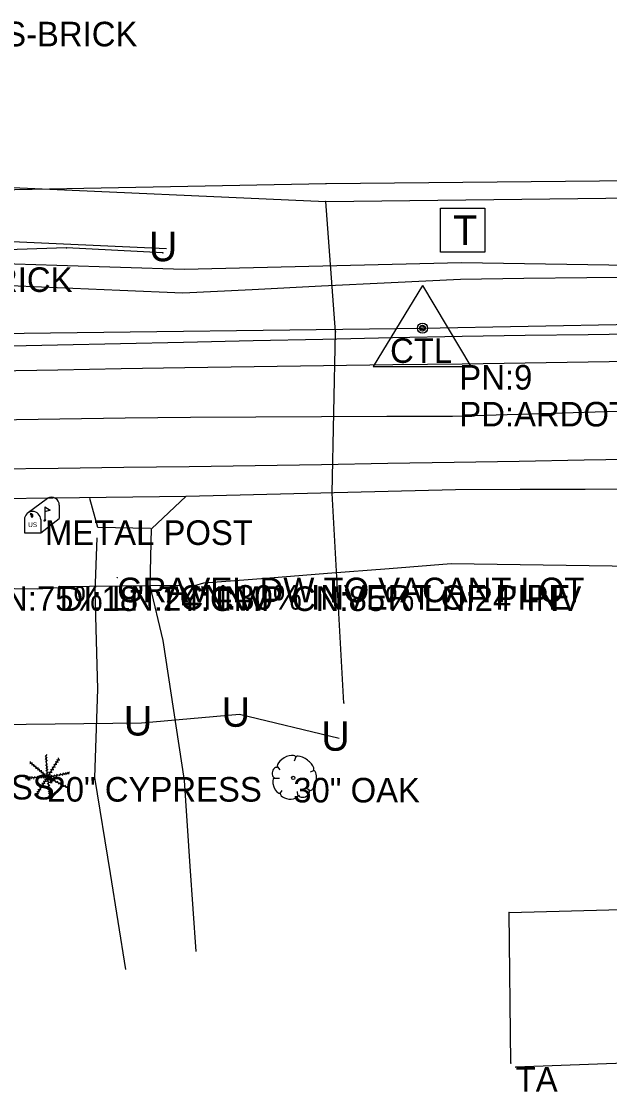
# Model space of a CAD drawing. Extents: x 1800653 to 1804042, y 522635 to 523313.
# Drawn here: x 1803016.3 to 1803136, y 522858.3 to 523076 of the extents above; entities that cross this region are included whole.
import ezdxf

# ---------------------------------------------------------------- set-up
doc = ezdxf.new("R2010")
doc.units = 0
for name, color, linetype in [('Default', 7, 'Continuous'), ('S_BASELINE', 7, 'Continuous'), ('S_BUILDING', 7, 'Continuous'), ('S_BUILDING_ANNOT', 7, 'Continuous'), ('S_DITCHLINE', 7, 'Continuous'), ('S_DRG_PT_SYM', 7, 'Continuous'), ('S_DRIVEWAY', 7, 'Continuous'), ('S_EDGE_PAVEMENT', 7, 'Continuous'), ('S_FIBER_OPTIC_CABLE', 7, 'Continuous'), ('S_GAS_UTILITIES', 7, 'Continuous'), ('S_MAILBOX', 7, 'Continuous'), ('S_MAILBOX_ANNOT', 7, 'Continuous'), ('S_MSC_PT_SYM', 7, 'Continuous'), ('S_PAVEMENT_CROWN', 7, 'Continuous'), ('S_PRIMARY_CTL', 7, 'Continuous'), ('S_PRIMARY_CTL_ANNOT', 7, 'Continuous'), ('S_SHOULDER', 7, 'Continuous'), ('S_SIDE_DRAIN', 7, 'Continuous'), ('S_SIDE_DRAIN_ANNOT', 7, 'Continuous'), ('S_STR_PT_SYM', 7, 'Continuous'), ('S_SURVEY_TEXT_ANNOT', 7, 'Continuous'), ('S_TELEPHONE_UTILITIES', 7, 'Continuous'), ('S_TREE', 7, 'Continuous'), ('S_TREE_ANNOT', 7, 'Continuous'), ('S_UNDERGROUND_CABLE', 7, 'Continuous'), ('S_UTL_PT_SYM', 7, 'Continuous'), ('S_WATER_UTILITIES', 7, 'Continuous')]:
    doc.layers.add(name, color=color, linetype=linetype)

msp = doc.modelspace()

# ---------------------------------------------------------------- linework, layer by layer
at = {"layer": 'S_BASELINE'}
for p, q in [((1803097.96, 523013.6), (1803914.71, 523028.84)), ((1802220.63, 523002.66), (1803097.96, 523013.6))]:
    msp.add_line(p, q, dxfattribs=at)
at = {"layer": 'S_BUILDING'}
for p, q in [((1803115.61, 522894.68), (1803141.73, 522895.4)), ((1803115.93, 522864.06), (1803115.61, 522894.68)), ((1803174.89, 522865.35), (1803116.93, 522863.25))]:
    msp.add_line(p, q, dxfattribs=at)
at = {"layer": 'S_DITCHLINE'}
for points in [[(1802954.76, 523027.19), (1802965.25, 523026.85), (1802981.47, 523027.06), (1802997.7, 523027.27), (1803010.63, 523026.85), (1803023.56, 523026.42), (1803036.49, 523025.99), (1803049.42, 523025.57), (1803063.54, 523025.91), (1803077.66, 523026.26), (1803091.77, 523026.61), (1803105.89, 523026.96), (1803118.74, 523026.75), (1803131.59, 523026.53), (1803144.45, 523026.32), (1803157.3, 523026.11), (1803171.75, 523026.51), (1803186.19, 523026.9), (1803200.64, 523027.3), (1803215.09, 523027.7), (1803229.41, 523027.72), (1803243.73, 523027.74), (1803258.05, 523027.76), (1803272.38, 523027.78)], [(1802954.86, 523026.08), (1802964.7, 523024.61), (1802981.39, 523023.77), (1802998.08, 523022.92), (1803010.85, 523022.39), (1803023.62, 523021.85), (1803036.38, 523021.31), (1803049.15, 523020.77), (1803063.29, 523021.48), (1803077.43, 523022.18), (1803091.58, 523022.88), (1803105.72, 523023.58), (1803118.57, 523023.74), (1803131.43, 523023.9), (1803144.29, 523024.05), (1803157.14, 523024.21), (1803171.66, 523024.43), (1803186.19, 523024.65), (1803200.71, 523024.88), (1803215.23, 523025.1), (1803229.37, 523025.17), (1803243.51, 523025.24), (1803257.65, 523025.32), (1803271.78, 523025.39)], [(1803049.77, 522960.68), (1803053.46, 522961.77), (1803066.04, 522962.75), (1803078.62, 522963.73), (1803091.2, 522964.71), (1803103.78, 522965.69), (1803117.85, 522965.49), (1803131.92, 522965.3), (1803146, 522965.1), (1803160.07, 522964.91), (1803174.22, 522961.96)], [(1802962.08, 522882.48), (1802961.64, 522899.88), (1802961.2, 522917.27), (1802961.74, 522932.63), (1802962.27, 522947.99), (1802966.05, 522961.46), (1802981.02, 522961.17), (1802996, 522960.89), (1803019.65, 522960.53), (1803023.7, 522960.83)]]:
    msp.add_lwpolyline(points, dxfattribs=at)
at = {"layer": 'S_DRG_PT_SYM'}
for points in [[(1803048.53, 522961.31), (1803048.53, 522961.36), (1803048.53, 522961.31), (1803048.48, 522961.31), (1803048.53, 522961.31), (1803048.53, 522961.26), (1803048.53, 522961.31), (1803048.58, 522961.31)], [(1803024.08, 522961.05), (1803024.08, 522961.1), (1803024.08, 522961.05), (1803024.03, 522961.05), (1803024.08, 522961.05), (1803024.08, 522961), (1803024.08, 522961.05), (1803024.13, 522961.05)]]:
    msp.add_lwpolyline(points, dxfattribs=at)
at = {"layer": 'S_DRIVEWAY'}
for points in [[(1803042.57, 522972.81), (1803031.87, 522973.02), (1803030.22, 522978.97)], [(1803042.77, 522972.79), (1803049.84, 522979.41)], [(1803051.89, 522886.77), (1803050.7, 522904.15), (1803049.52, 522921.53), (1803047.34, 522935.77), (1803045.16, 522950.01), (1803042.51, 522961.15), (1803042.81, 522972.85)], [(1803037.6, 522883.12), (1803034.45, 522902.66), (1803031.29, 522922.19), (1803031.9, 522940.15), (1803031.35, 522959.89), (1803031.72, 522970.95)]]:
    msp.add_lwpolyline(points, dxfattribs=at)
at = {"layer": 'S_EDGE_PAVEMENT'}
for points in [[(1803010.82, 523004.9), (1803023.74, 523005.13), (1803036.65, 523005.36), (1803049.57, 523005.6), (1803063.69, 523005.79), (1803077.82, 523005.98), (1803091.94, 523006.17), (1803106.07, 523006.37), (1803118.88, 523006.55), (1803131.69, 523006.74), (1803144.5, 523006.93)], [(1802793.98, 522981.33), (1802808.56, 522981.56), (1802832.98, 522981.95), (1802857.39, 522982.34), (1802874.9, 522982.71), (1802892.4, 522983.08), (1802910.08, 522983.28), (1802927.76, 522983.47), (1802945.52, 522983.73), (1802963.29, 522983.99), (1802980.26, 522984.41), (1802997.22, 522984.84), (1803010.53, 522984.99), (1803023.83, 522985.13), (1803037.14, 522985.28), (1803050.45, 522985.42), (1803063.93, 522985.65), (1803077.42, 522985.88), (1803090.9, 522986.1), (1803104.39, 522986.33), (1803117.62, 522986.56), (1803130.85, 522986.79), (1803144.08, 522987.01)]]:
    msp.add_lwpolyline(points, dxfattribs=at)
at = {"layer": 'S_FIBER_OPTIC_CABLE'}
for p, q in [((1803025.5, 523029.94), (1802984.52, 523028.61)), ((1803045.14, 523028.93), (1803025.5, 523029.94))]:
    msp.add_line(p, q, dxfattribs=at)
at = {"layer": 'S_GAS_UTILITIES'}
for p, q in [((1802933.65, 523045.78), (1803078.29, 523039.38)), ((1803078.29, 523039.38), (1803309.15, 523042.1)), ((1803080.27, 523012.85), (1803078.29, 523039.38)), ((1803079.56, 522980.04), (1803080.27, 523012.85)), ((1803081.98, 522937.31), (1803079.56, 522980.04))]:
    msp.add_line(p, q, dxfattribs=at)
at = {"layer": 'S_MAILBOX'}
for p, q in [((1803017.48, 522975.92), (1803021.61, 522979.03)), ((1803021.09, 522977.21), (1803021.09, 522974.49)), ((1803024.04, 522977.55), (1803024.04, 522974.84)), ((1803016.92, 522974.64), (1803016.92, 522971.93)), ((1803020.25, 522971.93), (1803024.04, 522974.84)), ((1803020.25, 522974.64), (1803020.25, 522971.93)), ((1803016.92, 522971.93), (1803020.25, 522971.93))]:
    msp.add_line(p, q, dxfattribs=at)
for points in [[(1803021.09, 522977.21), (1803022.2, 522976.54), (1803021.09, 522976.19)], [(1803018.11, 522975.76), (1803018.33, 522975.62), (1803018.33, 522975.23), (1803018.63, 522975.23), (1803018.63, 522975.59), (1803018.44, 522975.84), (1803018.11, 522975.79)]]:
    msp.add_lwpolyline(points, dxfattribs=at)
for centre, end in [((1803022.38, 522977.55), 117.5718), ((1803018.59, 522974.64), 180)]:
    msp.add_arc(centre, 1.66, 0, end, dxfattribs=at)
msp.add_ellipse((1803021.09, 522974.49), major_axis=(0.145, 0.132), ratio=0.564646, dxfattribs=at)
at = {"layer": 'S_MSC_PT_SYM'}
msp.add_lwpolyline([(1803035.83, 522962.83), (1803035.83, 522962.88), (1803035.83, 522962.83), (1803035.78, 522962.83), (1803035.83, 522962.83), (1803035.83, 522962.78), (1803035.83, 522962.83), (1803035.88, 522962.83)], dxfattribs=at)
at = {"layer": 'S_PAVEMENT_CROWN'}
msp.add_lwpolyline([(1802794.02, 522991.35), (1802808.65, 522991.45), (1802833.37, 522992.27), (1802858.09, 522993.08), (1802875.18, 522993.01), (1802892.27, 522992.94), (1802910.76, 522993.2), (1802929.25, 522993.47), (1802946.96, 522993.71), (1802964.67, 522993.95), (1802981.09, 522994.36), (1802997.51, 522994.76), (1803010.81, 522994.95), (1803024.11, 522995.13), (1803037.42, 522995.32), (1803050.72, 522995.5), (1803064.06, 522995.56), (1803077.39, 522995.61), (1803090.73, 522995.66), (1803104.06, 522995.72), (1803117.45, 522996.1), (1803130.84, 522996.49), (1803144.23, 522996.88)], dxfattribs=at)
at = {"layer": 'S_PRIMARY_CTL'}
for p, q in [((1803097.96, 523022.3), (1803087.93, 523005.79)), ((1803097.96, 523022.3), (1803107.78, 523005.79)), ((1803087.93, 523005.79), (1803107.78, 523005.79))]:
    msp.add_line(p, q, dxfattribs=at)
for radius in [1.04, 0.609, 0.344]:
    msp.add_circle((1803097.96, 523013.6), radius, dxfattribs=at)
at = {"layer": 'S_SHOULDER'}
for points in [[(1803010.87, 523009.91), (1803023.68, 523010.2), (1803036.48, 523010.48), (1803049.29, 523010.77), (1803063.49, 523011.08), (1803077.68, 523011.38), (1803091.88, 523011.69), (1803106.07, 523012), (1803118.87, 523012.17), (1803131.66, 523012.34), (1803144.46, 523012.52)], [(1802793.86, 522975.94), (1802808.36, 522976.14), (1802832.74, 522976.63), (1802857.12, 522977.13), (1802874.52, 522977.23), (1802891.91, 522977.33), (1802909.78, 522977.47), (1802927.64, 522977.61), (1802945.31, 522977.97), (1802962.99, 522978.33), (1802984.7, 522978.6), (1803006.42, 522978.88), (1803028.14, 522979.15), (1803049.85, 522979.42), (1803063.55, 522979.76), (1803077.25, 522980.09), (1803090.95, 522980.43), (1803104.65, 522980.76), (1803117.85, 522980.81), (1803131.05, 522980.86), (1803144.24, 522980.9)]]:
    msp.add_lwpolyline(points, dxfattribs=at)
at = {"layer": 'S_SIDE_DRAIN'}
msp.add_line((1803024.08, 522961.05), (1803048.53, 522961.31), dxfattribs=at)
at = {"layer": 'S_STR_PT_SYM'}
for points in [[(1803115.61, 522894.68), (1803115.61, 522894.73), (1803115.61, 522894.68), (1803115.56, 522894.68), (1803115.61, 522894.68), (1803115.61, 522894.63), (1803115.61, 522894.68), (1803115.66, 522894.68)], [(1803115.93, 522864.06), (1803115.93, 522864.11), (1803115.93, 522864.06), (1803115.88, 522864.06), (1803115.93, 522864.06), (1803115.93, 522864.01), (1803115.93, 522864.06), (1803115.98, 522864.06)], [(1803116.93, 522863.25), (1803116.93, 522863.3), (1803116.93, 522863.25), (1803116.88, 522863.25), (1803116.93, 522863.25), (1803116.93, 522863.2), (1803116.93, 522863.25), (1803116.98, 522863.25)]]:
    msp.add_lwpolyline(points, dxfattribs=at)
at = {"layer": 'S_TELEPHONE_UTILITIES'}
msp.add_lwpolyline([(1803101.66, 523029.04), (1803101.66, 523038.04), (1803110.66, 523038.04), (1803110.66, 523029.04)], close=True, dxfattribs=at)
at = {"layer": 'S_TREE'}
for p, q in [((1803021.37, 522926.34), (1803021.15, 522926.54)), ((1803021.63, 522922.26), (1803021.36, 522926.7)), ((1803021.37, 522926.59), (1803021.56, 522926.82)), ((1803018.35, 522925), (1803018.05, 522924.96)), ((1803021.63, 522922.26), (1803018.16, 522925.17)), ((1803018.2, 522925.14), (1803018.2, 522925.44)), ((1803018.69, 522924.73), (1803018.39, 522924.7)), ((1803018.52, 522924.89), (1803018.52, 522925.19)), ((1803019.06, 522924.4), (1803018.76, 522924.38)), ((1803018.87, 522924.6), (1803018.87, 522924.9)), ((1803019.29, 522924.24), (1803019.29, 522924.54)), ((1803021.41, 522925.78), (1803021.18, 522925.98)), ((1803021.44, 522925.2), (1803021.21, 522925.4)), ((1803021.46, 522924.54), (1803021.24, 522924.74)), ((1803021.4, 522926.11), (1803021.59, 522926.34)), ((1803021.43, 522925.51), (1803021.62, 522925.74)), ((1803021.47, 522924.8), (1803021.66, 522925.03)), ((1803021.54, 522924.23), (1803021.72, 522924.47)), ((1803021.63, 522922.26), (1803023.97, 522925.94)), ((1803022.73, 522924.04), (1803022.64, 522924.32)), ((1803022.95, 522924.27), (1803023.24, 522924.32)), ((1803023.11, 522924.6), (1803023.02, 522924.89)), ((1803023.27, 522924.82), (1803023.56, 522924.86)), ((1803023.4, 522925.12), (1803023.31, 522925.41)), ((1803023.59, 522925.31), (1803023.89, 522925.35)), ((1803023.7, 522925.57), (1803023.61, 522925.86)), ((1803023.84, 522925.73), (1803024.13, 522925.78)), ((1803023.95, 522925.91), (1803023.86, 522926.2)), ((1803068.42, 522924.32), (1803068.92, 522923.74)), ((1803072.21, 522926.34), (1803071.83, 522925.48)), ((1803021.63, 522922.26), (1803017.18, 522922.05)), ((1803017.41, 522922.07), (1803017.24, 522922.32)), ((1803017.8, 522922.1), (1803017.63, 522922.35)), ((1803017.95, 522922.09), (1803017.82, 522921.82)), ((1803018.2, 522922.1), (1803018.03, 522922.35)), ((1803018.37, 522922.11), (1803018.24, 522921.84)), ((1803018.6, 522922.12), (1803018.43, 522922.37)), ((1803018.88, 522922.13), (1803018.75, 522921.86)), ((1803019.17, 522922.14), (1803019, 522922.38)), ((1803019.51, 522924.03), (1803019.21, 522924)), ((1803021.63, 522922.26), (1803019.25, 522918.49)), ((1803019.44, 522922.16), (1803019.31, 522921.89)), ((1803019.72, 522922.17), (1803019.55, 522922.42)), ((1803019.87, 522923.7), (1803019.58, 522923.68)), ((1803019.7, 522923.91), (1803019.7, 522924.21)), ((1803019.93, 522922.18), (1803019.79, 522921.91)), ((1803020.21, 522923.44), (1803019.91, 522923.41)), ((1803020.02, 522923.63), (1803020.02, 522923.93)), ((1803020.2, 522922.19), (1803020.03, 522922.44)), ((1803020.55, 522923.14), (1803020.25, 522923.11)), ((1803020.4, 522922.2), (1803020.26, 522921.93)), ((1803020.39, 522923.33), (1803020.39, 522923.63)), ((1803020.64, 522922.23), (1803020.47, 522922.47)), ((1803020.92, 522922.84), (1803020.62, 522922.82)), ((1803020.86, 522922.21), (1803020.72, 522921.94)), ((1803020.76, 522923.02), (1803020.76, 522923.32)), ((1803020.97, 522922.27), (1803020.8, 522922.51)), ((1803021.28, 522922.54), (1803020.98, 522922.52)), ((1803021.11, 522922.71), (1803021.11, 522923.01)), ((1803021.24, 522922.22), (1803021.11, 522921.95)), ((1803021.5, 522923.95), (1803021.28, 522924.15)), ((1803021.54, 522923.38), (1803021.31, 522923.58)), ((1803021.55, 522922.76), (1803021.33, 522922.96)), ((1803021.55, 522923.67), (1803021.74, 522923.9)), ((1803021.57, 522922.99), (1803021.76, 522923.23)), ((1803021.63, 522922.26), (1803026.05, 522923.13)), ((1803021.63, 522922.26), (1803025.55, 522920.22)), ((1803021.63, 522922.26), (1803022.16, 522917.89)), ((1803021.96, 522922.08), (1803022.22, 522922.22)), ((1803021.98, 522922.75), (1803022.27, 522922.8)), ((1803022.07, 522923.02), (1803021.99, 522923.3)), ((1803022.01, 522922.35), (1803022.21, 522922.57)), ((1803022.25, 522922.38), (1803022.5, 522922.22)), ((1803022.26, 522923.22), (1803022.56, 522923.26)), ((1803022.44, 522923.54), (1803022.35, 522923.83)), ((1803022.41, 522922.4), (1803022.61, 522922.63)), ((1803022.6, 522923.76), (1803022.89, 522923.8)), ((1803022.76, 522922.45), (1803023.02, 522922.29)), ((1803022.93, 522922.51), (1803023.14, 522922.73)), ((1803023.28, 522922.57), (1803023.53, 522922.41)), ((1803023.5, 522922.64), (1803023.7, 522922.86)), ((1803023.89, 522922.7), (1803024.14, 522922.54)), ((1803024.13, 522922.78), (1803024.34, 522923)), ((1803024.47, 522922.8), (1803024.72, 522922.64)), ((1803024.73, 522922.87), (1803024.93, 522923.09)), ((1803024.98, 522922.92), (1803025.23, 522922.76)), ((1803025.21, 522922.97), (1803025.41, 522923.19)), ((1803025.4, 522923.01), (1803025.66, 522922.85)), ((1803025.66, 522923.06), (1803025.86, 522923.28)), ((1803025.81, 522923.07), (1803026.06, 522922.91)), ((1803025.88, 522923.11), (1803026.09, 522923.34)), ((1803075.78, 522923.55), (1803075.12, 522923.27)), ((1803017.26, 522922.05), (1803017.13, 522921.78)), ((1803017.61, 522922.07), (1803017.48, 522921.81)), ((1803020.27, 522920.11), (1803019.97, 522920.08)), ((1803020.53, 522920.53), (1803020.23, 522920.5)), ((1803020.42, 522920.33), (1803020.49, 522920.04)), ((1803020.78, 522920.95), (1803020.49, 522920.92)), ((1803020.67, 522920.75), (1803020.75, 522920.46)), ((1803021.06, 522921.4), (1803020.76, 522921.36)), ((1803020.93, 522921.16), (1803021.01, 522920.87)), ((1803021.3, 522921.76), (1803021, 522921.73)), ((1803021.21, 522921.6), (1803021.29, 522921.31)), ((1803021.42, 522921.94), (1803021.5, 522921.65)), ((1803021.69, 522921.58), (1803021.49, 522921.36)), ((1803021.76, 522921), (1803021.56, 522920.78)), ((1803021.84, 522920.44), (1803021.64, 522920.22)), ((1803021.71, 522921.84), (1803021.96, 522921.68)), ((1803021.75, 522921.28), (1803022, 522921.12)), ((1803021.83, 522920.71), (1803022.09, 522920.56)), ((1803021.89, 522920.16), (1803022.15, 522920.01)), ((1803022.14, 522921.98), (1803022.21, 522921.69)), ((1803022.44, 522921.85), (1803022.7, 522921.99)), ((1803022.72, 522921.68), (1803022.79, 522921.39)), ((1803022.99, 522921.55), (1803023.26, 522921.69)), ((1803023.26, 522921.4), (1803023.33, 522921.11)), ((1803023.55, 522921.27), (1803023.81, 522921.41)), ((1803023.78, 522921.13), (1803023.85, 522920.84)), ((1803024.03, 522921.01), (1803024.29, 522921.15)), ((1803024.31, 522920.84), (1803024.38, 522920.54)), ((1803024.56, 522920.74), (1803024.83, 522920.88)), ((1803024.83, 522920.58), (1803024.9, 522920.29)), ((1803025.11, 522920.46), (1803025.38, 522920.6)), ((1803025.32, 522920.33), (1803025.39, 522920.03)), ((1803025.51, 522920.25), (1803025.77, 522920.39)), ((1803067.76, 522922), (1803068.88, 522922)), ((1803019.28, 522918.57), (1803018.98, 522918.54)), ((1803019.48, 522918.87), (1803019.18, 522918.84)), ((1803019.4, 522918.73), (1803019.48, 522918.44)), ((1803019.73, 522919.29), (1803019.43, 522919.25)), ((1803019.63, 522919.08), (1803019.7, 522918.79)), ((1803019.97, 522919.66), (1803019.67, 522919.63)), ((1803019.89, 522919.48), (1803019.96, 522919.19)), ((1803020.13, 522919.86), (1803020.21, 522919.57)), ((1803021.91, 522919.88), (1803021.71, 522919.65)), ((1803021.97, 522919.42), (1803021.78, 522919.19)), ((1803022.01, 522919.04), (1803021.82, 522918.81)), ((1803022.07, 522918.59), (1803021.88, 522918.36)), ((1803022.12, 522918.17), (1803021.92, 522917.94)), ((1803021.96, 522919.65), (1803022.22, 522919.5)), ((1803022, 522919.22), (1803022.25, 522919.07)), ((1803022.04, 522918.82), (1803022.3, 522918.66)), ((1803022.11, 522918.35), (1803022.36, 522918.2)), ((1803022.15, 522918.01), (1803022.4, 522917.85)), ((1803068.92, 522918.82), (1803069.39, 522919.52)), ((1803072.6, 522918.55), (1803072.52, 522919.32)), ((1803075, 522919.44), (1803074.54, 522919.86))]:
    msp.add_line(p, q, dxfattribs=at)
msp.add_circle((1803071.66, 522922.09), 0.341, dxfattribs=at)
for centre, major_axis, ratio, start_param, end_param in [((1803070.32, 522925.29), (1.86, 1.08), 0.471018, 0, 3.141593), ((1803073.98, 522924.97), (-1.81, 1.36), 0.405113, 3.141593, 6.283186), ((1803068.09, 522923.18), (0.31, 1.03), 0.646762, 0, 3.141593), ((1803068.39, 522920.53), (-0.61, 1.6), 0.420543, 6.283185, 9.424777), ((1803075.33, 522921.56), (0.46, 2.04), 0.482994, 3.141593, 6.283185), ((1803070.85, 522918.75), (-1.83, 0.19), 0.529943, 0, 3.141593), ((1803073.81, 522919.04), (1.09, 0.46), 0.711534, 3.141592, 6.283185)]:
    msp.add_ellipse(centre, major_axis=major_axis, ratio=ratio, start_param=start_param, end_param=end_param, dxfattribs=at)
at = {"layer": 'S_UNDERGROUND_CABLE'}
for p, q in [((1803045.88, 523029.75), (1802972.62, 523033.05)), ((1802977.79, 522932.53), (1803040.79, 522933.26)), ((1803040.79, 522933.26), (1803060.71, 522935.03)), ((1803060.71, 522935.03), (1803081, 522930.15))]:
    msp.add_line(p, q, dxfattribs=at)
at = {"layer": 'S_UTL_PT_SYM'}
for points in [[(1803078.38, 523043.05), (1803078.38, 523043.1), (1803078.38, 523043.05), (1803078.33, 523043.05), (1803078.38, 523043.05), (1803078.38, 523043), (1803078.38, 523043.05), (1803078.43, 523043.05)], [(1803078.29, 523039.38), (1803078.29, 523039.43), (1803078.29, 523039.38), (1803078.24, 523039.38), (1803078.29, 523039.38), (1803078.29, 523039.33), (1803078.29, 523039.38), (1803078.34, 523039.38)], [(1803078.29, 523039.38), (1803078.29, 523039.43), (1803078.29, 523039.38), (1803078.24, 523039.38), (1803078.29, 523039.38), (1803078.29, 523039.33), (1803078.29, 523039.38), (1803078.34, 523039.38)], [(1803025.5, 523029.94), (1803025.5, 523029.99), (1803025.5, 523029.94), (1803025.45, 523029.94), (1803025.5, 523029.94), (1803025.5, 523029.89), (1803025.5, 523029.94), (1803025.55, 523029.94)], [(1803045.14, 523028.93), (1803045.14, 523028.98), (1803045.14, 523028.93), (1803045.09, 523028.93), (1803045.14, 523028.93), (1803045.14, 523028.88), (1803045.14, 523028.93), (1803045.19, 523028.93)], [(1803080.27, 523012.85), (1803080.27, 523012.9), (1803080.27, 523012.85), (1803080.22, 523012.85), (1803080.27, 523012.85), (1803080.27, 523012.8), (1803080.27, 523012.85), (1803080.32, 523012.85)], [(1803079.56, 522980.04), (1803079.56, 522980.09), (1803079.56, 522980.04), (1803079.51, 522980.04), (1803079.56, 522980.04), (1803079.56, 522979.99), (1803079.56, 522980.04), (1803079.61, 522980.04)], [(1803081.98, 522937.31), (1803081.98, 522937.36), (1803081.98, 522937.31), (1803081.93, 522937.31), (1803081.98, 522937.31), (1803081.98, 522937.26), (1803081.98, 522937.31), (1803082.03, 522937.31)]]:
    msp.add_lwpolyline(points, dxfattribs=at)
at = {"layer": 'S_WATER_UTILITIES'}
for p, q in [((1802956.08, 523040.62), (1803078.38, 523043.05)), ((1803078.38, 523043.05), (1803173.03, 523043.9))]:
    msp.add_line(p, q, dxfattribs=at)

# ---------------------------------------------------------------- texts
at = {"layer": 'Default'}
for p in [(1803042.25, 523027.21), (1803057.08, 522932.49), (1803037.16, 522930.71), (1803077.37, 522927.61)]:
    msp.add_text('U', height=6, dxfattribs=at).set_placement(p)
at = {"layer": 'S_BUILDING_ANNOT'}
msp.add_text('TA ', height=5, dxfattribs=at).set_placement((1803116.93, 522858.25))
at = {"layer": 'S_MAILBOX'}
msp.add_text('US', height=0.96, dxfattribs=at).set_placement((1803017.69, 522973.12))
at = {"layer": 'S_MAILBOX_ANNOT'}
msp.add_text('METAL POST', height=5, dxfattribs=at).set_placement((1803021.09, 522969.49))
at = {"layer": 'S_PRIMARY_CTL'}
msp.add_text('CTL', height=5, dxfattribs=at).set_placement((1803091.37, 523006.53))
at = {"layer": 'S_PRIMARY_CTL_ANNOT'}
for s, p in [('PN:9', (1803105.46, 523001.1)), ('PD:ARDOT STD CAP STAMPED PN:9', (1803105.46, 522993.6))]:
    msp.add_text(s, height=5, dxfattribs=at).set_placement(p)
at = {"layer": 'S_SIDE_DRAIN_ANNOT'}
for s, p in [('CN:30% INVERT OF PIPE', (1803048.53, 522956.31)), ('DI:18" TY:CMP CN:75% LN:24\' INV', (1802960.64, 522956.09)), ('DI:18" TY:CMP CN:85% LN:24\' INV', (1803024.08, 522956.05))]:
    msp.add_text(s, height=5, dxfattribs=at).set_placement(p)
at = {"layer": 'S_SURVEY_TEXT_ANNOT'}
for s, p in [('GRAVEL DW TO 1-S-BRICK', (1802953.74, 523070.94)), ('PAVED DW TO 1-S-BRICK', (1802944.99, 523020.97)), ('GRAVEL DW TO VACANT LOT', (1803035.83, 522957.83))]:
    msp.add_text(s, height=5, dxfattribs=at).set_placement(p)
at = {"layer": 'S_TELEPHONE_UTILITIES'}
msp.add_text('T', height=6, dxfattribs=at).set_placement((1803104.22, 523030.54))
at = {"layer": 'S_TREE_ANNOT'}
for s, p in [('24" CYPRESS', (1802979.47, 522917.69)), ('20" CYPRESS', (1803021.63, 522917.26)), ('30" OAK', (1803071.66, 522917.09))]:
    msp.add_text(s, height=5, dxfattribs=at).set_placement(p)

doc.saveas('drawing.dxf')
